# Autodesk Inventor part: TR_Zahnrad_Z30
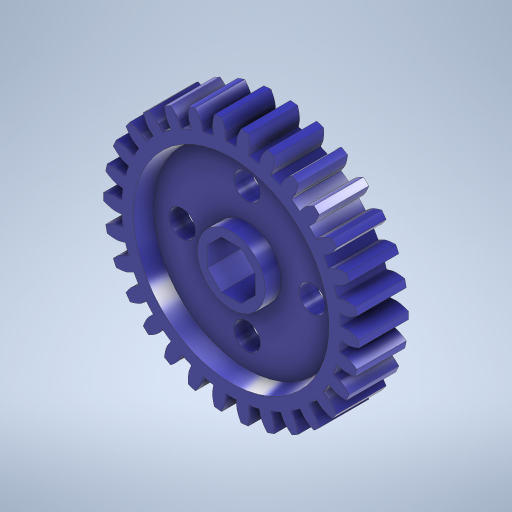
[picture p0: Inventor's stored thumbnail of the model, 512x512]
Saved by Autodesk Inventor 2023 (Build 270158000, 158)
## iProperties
Created: 2023-11
Part Number: TR_Zahnrad_Z30
Material: Generic
Document SubType Name: Modeling
Designer: AdminForWorker
Density: 1 g/cm^3
Appearance: Default
Title: Component1
Author: AdminForWorker
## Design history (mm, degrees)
feature "Body1"
workplane "Arbeitsebene1"
sketch "Skizze1"
  geometry: C1 r 11.75 at (-13.754, 6.632); C2 r 4.25 at (-13.754, 6.632); 1 further point
  constraints: 2 centre point, 2 coincident
  dimensions: "d0" = 23.5 diameter of C1; "d3" = 8.5 diameter of C2
extrude "Extrusion1" cut sketch "Skizze1" distance "d1" = 2; taper "d2" = 0 deg
mirror "Spiegeln1"
sketch "Skizze2"
  geometry: C1 r 1.65 at (0, 8.15); 1 further point
  constraints: 1 centre point, 1 vertical alignment
  dimensions: "d4" = 3.3 diameter of C1; "d5" = 8.15 distance of point (0, 0) C1.centre
extrude "Extrusion2" cut sketch "Skizze2" extent not by distance; stored distance "d6" = 0; taper "d7" = 0 deg
pattern_circular "Runde Anordnung1" dims angle "d9" = 360 deg
sketch "Skizze3"
  geometry: L1 (-1.243, 3)-(1.243, 3); L2 (1.243, 3)-(3, 1.243); L3 (3, 1.243)-(3, -1.243); L4 (3, -1.243)-(1.243, -3); L5 (1.243, -3)-(-1.243, -3); L6 (-1.243, -3)-(-3, -1.243); L7 (-3, -1.243)-(-3, 1.243); L8 (-3, 1.243)-(-1.243, 3); C1 r 4.25 at (0, 0) reference; 2 further points
  constraints: 16 end point, 1 coincident, 1 horizontal, 17 other
  dimensions: "d11" = 6 distance between parallel lines of L7 L3 (= AchteckUmkreis)
extrude "Extrusion3" cut sketch "Skizze3" extent not by distance; stored distance "d12" = 0; taper "d13" = 0 deg
chamfer "Fase1" distance "d14" = 0.5; stored, may be unused: second distance "d15" = 2, angle "d16" = 45 deg
chamfer "Fase2" distance "d17" = 0.5; stored, may be unused: second distance "d18" = 2, angle "d19" = 45 deg
body "Solid1"
other parameters: "Radius" = 2.075 [user parameter], "Fasen" = 0.5 [user parameter], "Dicke" = 0.8 [user parameter], "Breitloch" = 2 [user parameter], "Langloch" = 32 [user parameter], "AchteckUmkreis" = 6 [user parameter; used in 1 equation term], "DAchsAufnahme" = 4.1 [user parameter], "AchsDurchmesser" = 4 [user parameter], "AchsFase" = 0.5 [user parameter]
